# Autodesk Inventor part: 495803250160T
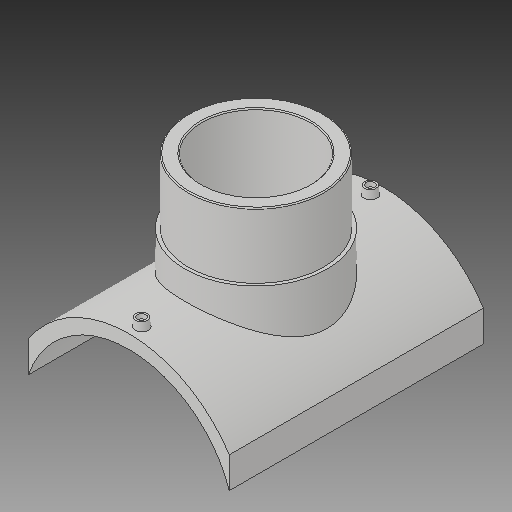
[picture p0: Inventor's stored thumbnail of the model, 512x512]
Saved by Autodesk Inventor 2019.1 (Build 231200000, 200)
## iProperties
Created: 2017-10
Part Number: 495803250160T
Material: Generic
Description: PLASSON BRANCH SADDLE 250x160
Document SubType Name: Modeling
Designer: KIM
Mass: 2754.05 g
Surface Area: 3037.44 cm^2
Volume: 2754.05 cm^3
Density: 1 g/cm^3
Appearance: Default
Author: KIM
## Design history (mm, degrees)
derived "495803.ipt"
feature "Solid1::495803.ipt"
tag "TaggingFeature1"
body "Solid1"
other parameters: "d1" = 16, "d2" = 237, "d4" = 0, "d12" = 150.6, "d13" = 14, "d14" = 135, "d16" = 5 deg, "d18" = 4, "d19" = 14, "d20" = 0, "d21" = 3, "d22" = 0, "d23" = 251, "d24" = 168, "d25" = 16, "d26" = 128, "d28" = 0, "d29" = 9.6, "d31" = 0, "d32" = 55, "d33" = 0, "d34" = 2.5, "d37" = 77, "d38" = 0, "d39" = 1.25, "B_" = 237, "x_" = 16, "D_" = 16
